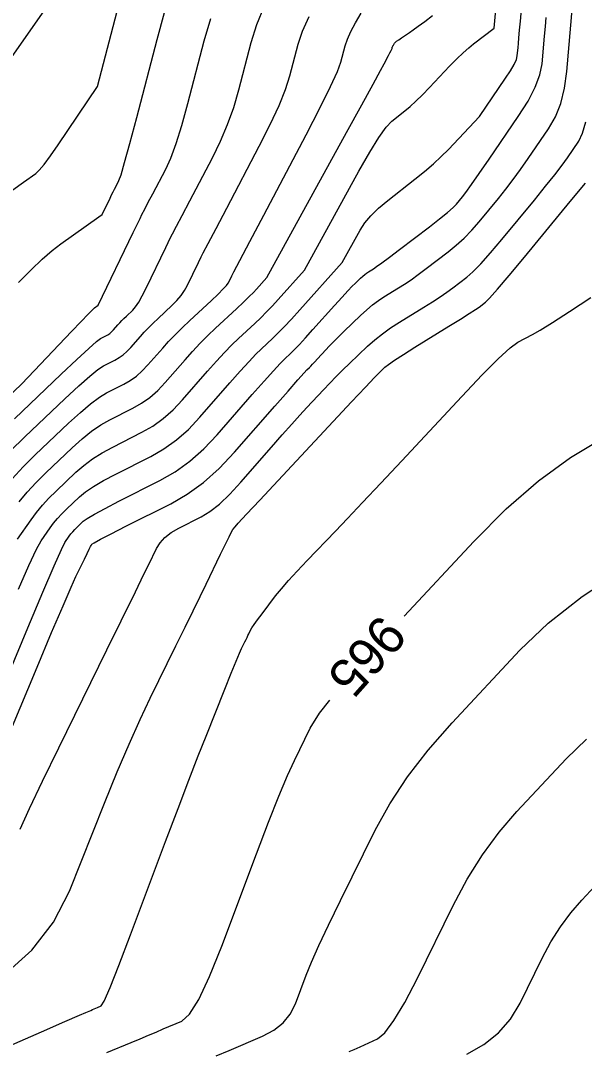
# Model space of a CAD drawing. Extents: x 2175772 to 2185556, y 721391 to 722853.
# Drawn here: x 2178711.9 to 2178754, y 721892.9 to 721969.8 of the extents above; entities that cross this region are included whole.
import ezdxf

# ---------------------------------------------------------------- set-up
doc = ezdxf.new("R2010")
doc.units = 0
doc.layers.add('DT_X_Contour_Major', color=7, linetype='Continuous')
doc.layers.add('DT_X_Contour_Minor', color=7, linetype='Continuous')

msp = doc.modelspace()

# ---------------------------------------------------------------- linework, layer by layer
at = {"layer": 'DT_X_Contour_Major'}
for points in [[(2178705.132, 721957.827), (2178705.785, 721959.035), (2178706.309, 721960.006), (2178706.486, 721960.33), (2178706.491, 721960.336), (2178706.493, 721960.338), (2178706.495, 721960.34), (2178706.497, 721960.341), (2178706.498, 721960.342), (2178706.504, 721960.347), (2178706.508, 721960.35), (2178706.516, 721960.361), (2178706.538, 721960.394), (2178706.575, 721960.448), (2178706.626, 721960.523), (2178706.782, 721960.753), (2178707.015, 721961.089), (2178707.6, 721961.925), (2178708.536, 721963.261), (2178709.823, 721965.097), (2178713.722, 721970.66)], [(2178709.092, 721916.445), (2178712.46, 721924.491), (2178713.58, 721927.153), (2178714.414, 721929.103), (2178714.963, 721930.341), (2178715.225, 721930.868), (2178715.543, 721931.324), (2178715.669, 721931.494), (2178715.809, 721931.664), (2178715.963, 721931.832), (2178716.131, 721931.998), (2178716.598, 721932.441), (2178716.895, 721932.66), (2178717.436, 721932.982), (2178718.222, 721933.408), (2178719.253, 721933.938), (2178722.327, 721935.489), (2178723.459, 721936.139), (2178724.548, 721936.925), (2178725.595, 721937.846), (2178726.6, 721938.903), (2178729.222, 721941.904), (2178730.108, 721942.911), (2178730.799, 721943.685), (2178731.294, 721944.225), (2178731.593, 721944.53), (2178732.132, 721945.032), (2178732.384, 721945.281), (2178732.738, 721945.653), (2178733.193, 721946.146), (2178733.75, 721946.761), (2178735.37, 721948.565), (2178735.921, 721949.175), (2178736.359, 721949.654), (2178736.684, 721950), (2178736.897, 721950.215), (2178737.313, 721950.612), (2178737.467, 721950.753), (2178737.616, 721950.878), (2178737.762, 721950.988), (2178737.903, 721951.081), (2178738.273, 721951.309), (2178738.499, 721951.464), (2178738.9, 721951.755), (2178739.475, 721952.185), (2178740.225, 721952.752), (2178742.458, 721954.448), (2178743.211, 721955.03), (2178743.799, 721955.505), (2178744.219, 721955.873), (2178744.473, 721956.133), (2178744.928, 721956.685), (2178745.18, 721957.015), (2178745.593, 721957.594), (2178746.169, 721958.421), (2178746.906, 721959.496), (2178749.089, 721962.692), (2178749.814, 721963.837), (2178750.351, 721964.875), (2178750.7, 721965.805), (2178750.862, 721966.627), (2178751.044, 721968.676), (2178751.108, 721969.409), (2178751.167, 721970.07)], [(2178711.149, 721937.677), (2178712.23, 721938.75), (2178715.231, 721941.601), (2178716.256, 721942.557), (2178717.078, 721943.285), (2178717.698, 721943.786), (2178718.117, 721944.06), (2178718.963, 721944.488), (2178719.275, 721944.667), (2178719.575, 721944.883), (2178719.863, 721945.137), (2178720.14, 721945.428), (2178720.862, 721946.254), (2178721.148, 721946.57), (2178721.463, 721946.9), (2178721.809, 721947.244), (2178722.184, 721947.601), (2178723.224, 721948.571), (2178723.588, 721948.935), (2178723.899, 721949.302), (2178724.157, 721949.671), (2178724.363, 721950.041), (2178725.199, 721951.775), (2178725.404, 721952.201), (2178725.556, 721952.497), (2178725.925, 721953.203), (2178726.511, 721954.319), (2178727.313, 721955.845), (2178729.742, 721960.461), (2178730.568, 721962.087), (2178731.225, 721963.504), (2178731.712, 721964.711), (2178732.031, 721965.709), (2178732.654, 721968.09), (2178732.973, 721969.054), (2178733.464, 721970.158)], [(2178740.572, 721925.361), (2178745.771, 721930.935), (2178748.19, 721933.366), (2178750.593, 721935.459), (2178752.981, 721937.211), (2178755.353, 721938.625)], [(2178718.369, 721892.752), (2178720.18, 721893.504), (2178720.839, 721893.779), (2178721.458, 721894.038), (2178722.037, 721894.282), (2178722.576, 721894.511), (2178723.959, 721895.102), (2178724.535, 721895.618), (2178725.223, 721896.724), (2178726.025, 721898.42), (2178726.939, 721900.706), (2178729.528, 721907.588), (2178730.434, 721909.959), (2178731.208, 721911.912), (2178731.851, 721913.447), (2178732.364, 721914.563), (2178733.555, 721916.982), (2178734.249, 721918.101), (2178735.002, 721919.078)]]:
    msp.add_lwpolyline(points, dxfattribs=at)
at = {"layer": 'DT_X_Contour_Minor'}
for points in [[(2178711.694, 721931.112), (2178712.704, 721932.559), (2178713.104, 721933.1), (2178713.549, 721933.637), (2178714.038, 721934.17), (2178714.571, 721934.699), (2178716.051, 721936.105), (2178716.639, 721936.619), (2178717.293, 721937.103), (2178718.013, 721937.559), (2178718.798, 721937.987), (2178720.981, 721939.089), (2178721.785, 721939.55), (2178722.559, 721940.108), (2178723.302, 721940.762), (2178724.016, 721941.513), (2178725.878, 721943.644), (2178726.546, 721944.396), (2178727.153, 721945.054), (2178727.7, 721945.619), (2178728.185, 721946.09), (2178729.399, 721947.221), (2178729.85, 721947.652), (2178730.293, 721948.093), (2178730.728, 721948.547), (2178731.154, 721949.011), (2178733.127, 721951.208), (2178737.185, 721958.605), (2178737.991, 721960.027), (2178738.67, 721961.124), (2178739.223, 721961.896), (2178739.65, 721962.343), (2178740.619, 721963.1), (2178741.007, 721963.422), (2178741.444, 721963.822), (2178741.93, 721964.299), (2178742.465, 721964.853), (2178743.958, 721966.433), (2178744.489, 721966.982), (2178744.963, 721967.445), (2178745.381, 721967.823), (2178745.741, 721968.114), (2178747.289, 721969.271), (2178747.528, 721972.015)], [(2178711.761, 721927.379), (2178712.539, 721929.147), (2178713.105, 721930.351), (2178713.46, 721930.99), (2178714.123, 721931.941), (2178714.387, 721932.297), (2178714.679, 721932.65), (2178715.001, 721933.001), (2178715.351, 721933.349), (2178716.324, 721934.273), (2178716.767, 721934.639), (2178717.365, 721935.042), (2178718.118, 721935.483), (2178719.026, 721935.962), (2178721.654, 721937.289), (2178722.622, 721937.845), (2178723.553, 721938.516), (2178724.448, 721939.304), (2178725.308, 721940.208), (2178727.55, 721942.774), (2178728.327, 721943.654), (2178728.976, 721944.37), (2178729.497, 721944.922), (2178729.889, 721945.31), (2178730.765, 721946.127), (2178731.137, 721946.489), (2178731.597, 721946.963), (2178732.143, 721947.55), (2178732.777, 721948.248), (2178735.938, 721951.768), (2178737.271, 721954.197), (2178737.615, 721954.726), (2178738.076, 721955.273), (2178738.655, 721955.837), (2178739.351, 721956.418), (2178741.362, 721957.99), (2178742.085, 721958.572), (2178742.743, 721959.138), (2178743.338, 721959.689), (2178743.868, 721960.225), (2178746.195, 721962.687), (2178748.139, 721965.534), (2178748.506, 721966.097), (2178748.774, 721966.566), (2178748.943, 721966.94), (2178749.013, 721967.22), (2178749.068, 721967.841), (2178749.094, 721968.139), (2178749.132, 721968.566), (2178749.18, 721969.123), (2178749.24, 721969.809), (2178749.414, 721971.811)], [(2178709.9, 721913.788), (2178713.143, 721921.536), (2178714.237, 721924.139), (2178715.086, 721926.136), (2178715.691, 721927.528), (2178716.051, 721928.315), (2178716.685, 721929.607), (2178716.895, 721930.035), (2178717.05, 721930.35), (2178717.149, 721930.552), (2178717.193, 721930.642), (2178717.235, 721930.73), (2178717.406, 721930.838), (2178717.887, 721931.096), (2178718.678, 721931.505), (2178719.779, 721932.064), (2178723.128, 721933.754), (2178724.367, 721934.47), (2178725.574, 721935.349), (2178726.749, 721936.392), (2178727.891, 721937.598), (2178730.894, 721941.033), (2178731.889, 721942.169), (2178732.621, 721943.001), (2178733.09, 721943.528), (2178733.297, 721943.75), (2178733.498, 721943.937), (2178733.592, 721944.03), (2178733.724, 721944.169), (2178733.894, 721944.353), (2178734.102, 721944.582), (2178734.706, 721945.255), (2178734.962, 721945.531), (2178735.277, 721945.854), (2178735.65, 721946.224), (2178736.082, 721946.64), (2178737.312, 721947.814), (2178737.767, 721948.231), (2178738.21, 721948.601), (2178738.639, 721948.924), (2178739.056, 721949.201), (2178740.152, 721949.875), (2178740.588, 721950.155), (2178741.076, 721950.489), (2178741.615, 721950.876), (2178742.206, 721951.317), (2178743.849, 721952.566), (2178744.456, 721953.058), (2178745.044, 721953.596), (2178745.614, 721954.182), (2178746.165, 721954.815), (2178747.608, 721956.564), (2178748.153, 721957.242), (2178748.705, 721957.965), (2178749.263, 721958.731), (2178749.828, 721959.541), (2178751.344, 721961.761), (2178751.855, 721962.652), (2178752.254, 721963.662), (2178752.539, 721964.789), (2178752.711, 721966.034), (2178753.019, 721969.511), (2178753.122, 721970.679)], [(2178710.712, 721956.761), (2178712.129, 721957.767), (2178713.06, 721958.428), (2178713.313, 721958.668), (2178713.673, 721959.106), (2178714.141, 721959.74), (2178714.716, 721960.572), (2178717.65, 721964.912), (2178719.277, 721971.13)], [(2178711.45, 721940.1), (2178714.958, 721943.433), (2178716.128, 721944.536), (2178717.006, 721945.346), (2178717.594, 721945.862), (2178717.89, 721946.085), (2178718.29, 721946.287), (2178718.438, 721946.372), (2178718.58, 721946.475), (2178718.717, 721946.595), (2178718.848, 721946.733), (2178719.19, 721947.124), (2178719.325, 721947.274), (2178719.475, 721947.43), (2178719.638, 721947.593), (2178719.816, 721947.762), (2178720.309, 721948.221), (2178720.51, 721948.453), (2178720.742, 721948.804), (2178721.007, 721949.274), (2178721.304, 721949.863), (2178722.764, 721952.891), (2178723.123, 721953.635), (2178723.27, 721953.926), (2178723.557, 721954.48), (2178723.984, 721955.296), (2178724.551, 721956.376), (2178726.25, 721959.606), (2178726.851, 721960.831), (2178727.379, 721962.084), (2178727.835, 721963.366), (2178728.218, 721964.676), (2178729.141, 721968.207), (2178729.562, 721969.553), (2178730.132, 721970.94)], [(2178711.768, 721950.274), (2178712.695, 721951.222), (2178713.531, 721952.023), (2178714.275, 721952.675), (2178714.927, 721953.18), (2178717.755, 721955.188), (2178718.015, 721955.373), (2178718.596, 721956.578), (2178718.716, 721956.826), (2178718.828, 721957.051), (2178718.931, 721957.255), (2178719.026, 721957.438), (2178719.266, 721957.895), (2178719.417, 721958.319), (2178719.688, 721959.246), (2178720.079, 721960.677), (2178720.591, 721962.611), (2178722.117, 721968.442), (2178722.674, 721970.446)], [(2178708.961, 721939.828), (2178712.001, 721942.716), (2178715.727, 721946.63), (2178716.433, 721947.37), (2178716.954, 721947.91), (2178717.29, 721948.25), (2178717.441, 721948.391), (2178717.715, 721948.586), (2178720.329, 721954.008), (2178720.841, 721955.069), (2178720.983, 721955.355), (2178721.188, 721955.756), (2178721.456, 721956.274), (2178721.788, 721956.907), (2178722.758, 721958.75), (2178723.134, 721959.575), (2178723.533, 721960.665), (2178723.957, 721962.022), (2178724.404, 721963.644), (2178725.629, 721968.325), (2178726.118, 721970)], [(2178711.289, 721935.61), (2178712.112, 721936.508), (2178713.01, 721937.4), (2178715.504, 721939.769), (2178716.383, 721940.578), (2178717.15, 721941.225), (2178717.803, 721941.711), (2178718.344, 721942.036), (2178719.636, 721942.688), (2178720.112, 721942.961), (2178720.569, 721943.291), (2178721.009, 721943.679), (2178721.432, 721944.123), (2178722.534, 721945.384), (2178722.97, 721945.867), (2178723.452, 721946.371), (2178723.979, 721946.895), (2178724.552, 721947.44), (2178726.139, 721948.92), (2178726.666, 721949.417), (2178727.055, 721949.8), (2178727.307, 721950.067), (2178727.421, 721950.219), (2178727.633, 721950.659), (2178727.685, 721950.767), (2178727.843, 721951.068), (2178728.294, 721951.927), (2178729.039, 721953.342), (2178730.076, 721955.314), (2178733.234, 721961.316), (2178734.285, 721963.343), (2178735.071, 721964.923), (2178735.59, 721966.056), (2178735.844, 721966.741), (2178736.166, 721967.973), (2178736.331, 721968.471), (2178736.585, 721969.042), (2178736.927, 721969.686), (2178737.358, 721970.403)], [(2178711.822, 721933.902), (2178712.419, 721934.623), (2178713.075, 721935.339), (2178713.791, 721936.049), (2178715.778, 721937.937), (2178716.511, 721938.598), (2178717.221, 721939.164), (2178717.908, 721939.635), (2178718.571, 721940.011), (2178720.309, 721940.888), (2178720.948, 721941.256), (2178721.564, 721941.7), (2178722.156, 721942.22), (2178722.724, 721942.818), (2178724.206, 721944.514), (2178724.765, 721945.138), (2178725.331, 721945.739), (2178725.903, 721946.316), (2178726.481, 721946.87), (2178728.032, 721948.316), (2178728.562, 721948.814), (2178728.989, 721949.223), (2178729.312, 721949.543), (2178729.532, 721949.775), (2178730.316, 721950.649), (2178736.265, 721961.493), (2178737.396, 721963.556), (2178738.239, 721965.097), (2178738.794, 721966.115), (2178739.062, 721966.612), (2178739.393, 721967.241), (2178739.503, 721967.451), (2178739.583, 721967.61), (2178739.635, 721967.717), (2178739.657, 721967.774), (2178739.679, 721967.855), (2178739.69, 721967.888), (2178739.706, 721967.926), (2178739.729, 721967.969), (2178739.758, 721968.016), (2178739.842, 721968.15), (2178739.897, 721968.212), (2178740.002, 721968.301), (2178740.155, 721968.415), (2178740.356, 721968.555), (2178740.958, 721968.961), (2178741.235, 721969.154), (2178741.615, 721969.429), (2178742.099, 721969.784), (2178742.685, 721970.22)], [(2178711.875, 721909.442), (2178712.59, 721910.995), (2178713.557, 721913.023), (2178714.777, 721915.527), (2178718.366, 721922.837), (2178720.493, 721927.173), (2178721.132, 721928.48), (2178721.489, 721929.213), (2178722.065, 721930.403), (2178722.331, 721930.833), (2178722.699, 721931.23), (2178723.169, 721931.594), (2178723.741, 721931.925), (2178725.401, 721932.763), (2178726.053, 721933.16), (2178726.764, 721933.725), (2178727.533, 721934.456), (2178728.361, 721935.353), (2178730.648, 721937.969), (2178731.457, 721938.89), (2178732.168, 721939.691), (2178732.782, 721940.371), (2178733.298, 721940.932), (2178734.544, 721942.266), (2178735.016, 721942.764), (2178735.497, 721943.258), (2178735.988, 721943.747), (2178736.488, 721944.231), (2178737.835, 721945.516), (2178738.363, 721945.99), (2178738.934, 721946.449), (2178739.55, 721946.892), (2178740.21, 721947.32), (2178742.03, 721948.441), (2178742.677, 721948.846), (2178743.252, 721949.222), (2178743.755, 721949.567), (2178744.186, 721949.883), (2178745.241, 721950.684), (2178745.701, 721951.085), (2178746.29, 721951.687), (2178747.009, 721952.491), (2178747.856, 721953.496), (2178750.289, 721956.444), (2178751.127, 721957.469), (2178751.816, 721958.335), (2178752.357, 721959.041), (2178752.75, 721959.587), (2178753.598, 721960.83), (2178753.893, 721961.426), (2178754.142, 721962.282)], [(2178710.745, 721898.571), (2178712.768, 721900.398), (2178714.374, 721902.479), (2178715.566, 721904.814), (2178718.191, 721911.376), (2178719.142, 721913.712), (2178720.027, 721915.8), (2178720.846, 721917.638), (2178721.598, 721919.228), (2178723.516, 721923.135), (2178724.197, 721924.522), (2178724.798, 721925.753), (2178725.322, 721926.827), (2178725.767, 721927.746), (2178726.85, 721929.986), (2178727.213, 721930.731), (2178727.488, 721931.285), (2178727.677, 721931.648), (2178727.778, 721931.82), (2178727.933, 721932.024), (2178728.177, 721932.298), (2178728.793, 721932.967), (2178729.782, 721934.031), (2178731.142, 721935.49), (2178735.267, 721939.907), (2178736.641, 721941.376), (2178737.669, 721942.47), (2178738.352, 721943.189), (2178738.689, 721943.533), (2178739.127, 721943.951), (2178739.39, 721944.162), (2178739.851, 721944.48), (2178740.509, 721944.906), (2178741.364, 721945.44), (2178743.909, 721947.007), (2178744.765, 721947.538), (2178745.427, 721947.955), (2178745.894, 721948.258), (2178746.166, 721948.448), (2178746.632, 721948.802), (2178746.945, 721949.112), (2178747.536, 721949.778), (2178748.403, 721950.8), (2178749.548, 721952.177), (2178752.969, 721956.323), (2178754.1, 721957.696)], [(2178711.091, 721893.244), (2178713.476, 721894.295), (2178715.219, 721895.062), (2178716.321, 721895.546), (2178716.783, 721895.747), (2178717.159, 721895.903), (2178717.295, 721895.96), (2178717.424, 721896.013), (2178717.544, 721896.064), (2178717.656, 721896.112), (2178717.943, 721896.234), (2178718.16, 721896.601), (2178718.596, 721897.61), (2178719.251, 721899.261), (2178720.125, 721901.553), (2178722.747, 721908.523), (2178723.674, 721910.974), (2178724.486, 721913.103), (2178725.185, 721914.908), (2178725.77, 721916.39), (2178727.178, 721919.91), (2178727.652, 721921.089), (2178728.016, 721921.985), (2178728.272, 721922.598), (2178728.419, 721922.928), (2178728.667, 721923.432), (2178728.754, 721923.611), (2178728.832, 721923.769), (2178728.9, 721923.908), (2178728.957, 721924.026), (2178729.097, 721924.315), (2178729.19, 721924.472), (2178729.364, 721924.727), (2178729.62, 721925.08), (2178729.958, 721925.53), (2178730.966, 721926.86), (2178731.396, 721927.4), (2178731.931, 721928.021), (2178732.569, 721928.724), (2178733.311, 721929.508), (2178735.429, 721931.708), (2178736.334, 721932.655), (2178737.461, 721933.847), (2178738.811, 721935.284), (2178740.382, 721936.965), (2178744.868, 721941.774), (2178746.391, 721943.379), (2178747.596, 721944.587), (2178748.482, 721945.398), (2178749.05, 721945.811), (2178750.14, 721946.384), (2178750.72, 721946.72), (2178751.641, 721947.295), (2178752.903, 721948.11), (2178754.506, 721949.166)], [(2178726.53, 721892.5), (2178727.496, 721892.911), (2178729.976, 721893.969), (2178730.828, 721894.417), (2178731.523, 721894.969), (2178732.062, 721895.623), (2178732.445, 721896.381), (2178733.257, 721898.54), (2178733.645, 721899.495), (2178734.199, 721900.74), (2178734.92, 721902.276), (2178735.808, 721904.102), (2178738.397, 721909.36), (2178739.484, 721911.34), (2178740.804, 721913.337), (2178742.356, 721915.35), (2178744.142, 721917.38), (2178749.213, 721922.816), (2178751.325, 721924.836), (2178753.86, 721926.818), (2178756.816, 721928.763)], [(2178736.464, 721892.822), (2178736.841, 721892.981), (2178737.289, 721893.184), (2178738.577, 721893.783), (2178739.125, 721894.235), (2178739.803, 721895.139), (2178740.611, 721896.496), (2178741.549, 721898.306), (2178744.223, 721903.737), (2178745.273, 721905.704), (2178746.416, 721907.53), (2178747.652, 721909.216), (2178748.982, 721910.762), (2178752.654, 721914.698), (2178754.183, 721916.16)], [(2178745.237, 721892.639), (2178746.516, 721893.355), (2178747.607, 721894.227), (2178748.509, 721895.254), (2178749.224, 721896.437), (2178750.879, 721899.797), (2178751.528, 721901.014), (2178752.235, 721902.144), (2178753, 721903.188), (2178753.823, 721904.144), (2178756.095, 721906.579)]]:
    msp.add_lwpolyline(points, dxfattribs=at)

# ---------------------------------------------------------------- texts
at = {"layer": 'DT_X_Contour_Major'}
msp.add_text('965', height=2.8, rotation=228.44343, dxfattribs=at).set_placement((2178738.821, 721925.618))

doc.saveas('drawing.dxf')
